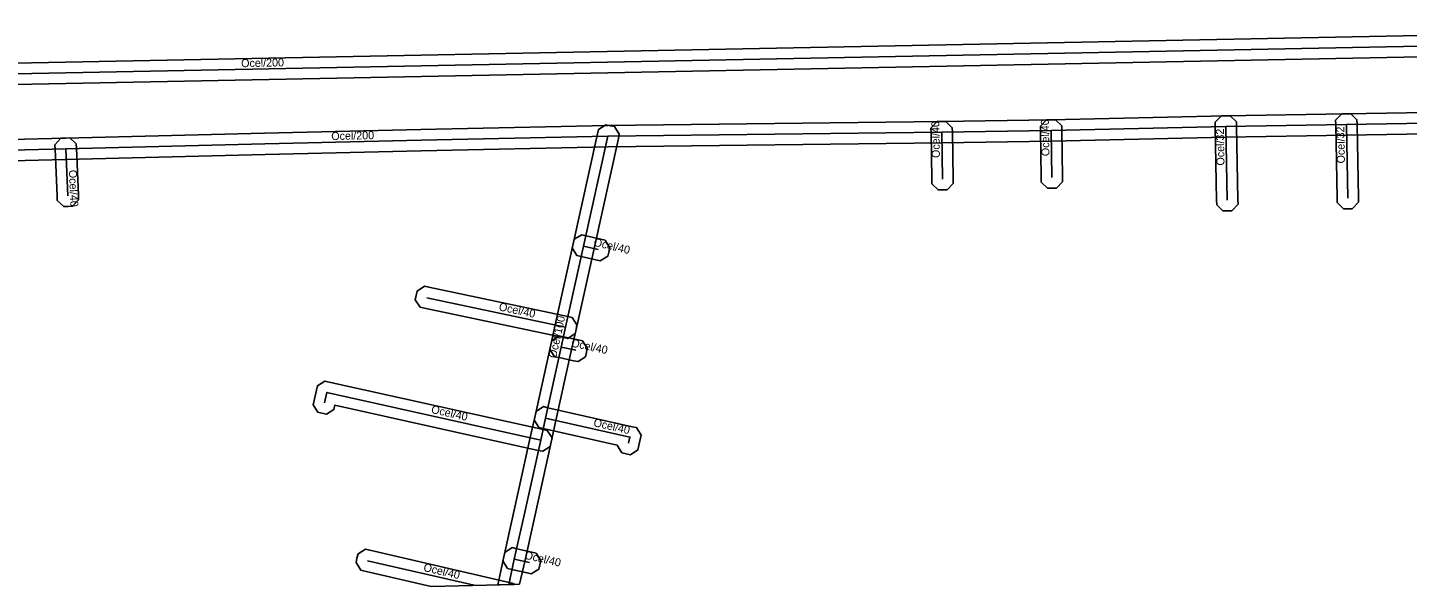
# Model space of a CAD drawing. Extents: x -702844 to -702342, y -1011731 to -1011542.
# Drawn here: x -702717.5 to -702588.2, y -1011727.3 to -1011674.9 of the extents above; entities that cross this region are included whole.
import ezdxf

# ---------------------------------------------------------------- set-up
doc = ezdxf.new("R2010")
doc.units = 0
for name, color, linetype in [('1', 7, 'Continuous'), ('14', 7, 'Continuous'), ('20', 7, 'Continuous'), ('24', 7, 'Continuous'), ('30', 7, 'Continuous')]:
    doc.layers.add(name, color=color, linetype=linetype)

msp = doc.modelspace()

# ---------------------------------------------------------------- linework, layer by layer
at = {"layer": '1'}
for points in [[(-702802.41, -1011681.9), (-702843.99, -1011682.6), (-702844.1, -1011680.6), (-702802.44, -1011679.9), (-702794.94, -1011679.78), (-702550.47, -1011674.95), (-702550.05, -1011674.94), (-702549.46, -1011675.51), (-702549.45, -1011675.93), (-702549.44, -1011676.34), (-702550.01, -1011676.94), (-702550.43, -1011676.95), (-702794.91, -1011681.78)], [(-702632.76, -1011689.58), (-702632.76, -1011689.16), (-702632.83, -1011684.76), (-702632.84, -1011684.35), (-702632.26, -1011683.75), (-702631.85, -1011683.75), (-702631.44, -1011683.74), (-702630.84, -1011684.32), (-702630.83, -1011684.73), (-702630.76, -1011689.13), (-702630.76, -1011689.55), (-702631.33, -1011690.14), (-702631.75, -1011690.15), (-702632.16, -1011690.15)], [(-702622.49, -1011689.41), (-702622.5, -1011689), (-702622.57, -1011684.6), (-702622.58, -1011684.19), (-702622, -1011683.59), (-702621.59, -1011683.58), (-702621.17, -1011683.58), (-702620.58, -1011684.15), (-702620.57, -1011684.57), (-702620.5, -1011688.97), (-702620.49, -1011689.38), (-702621.07, -1011689.98), (-702621.48, -1011689.98), (-702621.9, -1011689.99)], [(-702606.05, -1011691.54), (-702606.06, -1011691.12), (-702606.18, -1011684.22), (-702606.19, -1011683.81), (-702605.61, -1011683.21), (-702605.2, -1011683.21), (-702604.78, -1011683.2), (-702604.19, -1011683.78), (-702604.18, -1011684.19), (-702604.06, -1011691.09), (-702604.05, -1011691.5), (-702604.63, -1011692.1), (-702605.04, -1011692.1), (-702605.46, -1011692.11)], [(-702594.76, -1011691.34), (-702594.77, -1011690.93), (-702594.89, -1011684.03), (-702594.9, -1011683.62), (-702594.32, -1011683.02), (-702593.91, -1011683.01), (-702593.49, -1011683.01), (-702592.9, -1011683.58), (-702592.89, -1011684), (-702592.77, -1011690.9), (-702592.76, -1011691.31), (-702593.34, -1011691.91), (-702593.75, -1011691.91), (-702594.17, -1011691.92)], [(-702712.96, -1011685.83), (-702712.94, -1011686.24), (-702712.75, -1011690.65), (-702712.73, -1011691.07), (-702713.3, -1011691.68), (-702713.71, -1011691.69), (-702714.12, -1011691.71), (-702714.73, -1011691.15), (-702714.75, -1011690.74), (-702714.94, -1011686.33), (-702714.96, -1011685.92), (-702714.4, -1011685.31), (-702713.98, -1011685.29), (-702713.57, -1011685.27)], [(-702671.39, -1011727.11), (-702673.45, -1011727.16), (-702672.87, -1011724.53), (-702671.96, -1011720.44), (-702670.4, -1011713.37), (-702669.94, -1011711.32), (-702668.47, -1011704.67), (-702668.06, -1011702.8), (-702666.38, -1011695.2), (-702664.09, -1011684.9), (-702664, -1011684.49), (-702663.31, -1011684.05), (-702662.9, -1011684.14), (-702662.5, -1011684.22), (-702662.05, -1011684.92), (-702662.14, -1011685.33), (-702664.42, -1011695.63), (-702666.1, -1011703.23), (-702666.52, -1011705.1), (-702667.99, -1011711.75), (-702668.45, -1011713.8), (-702670.01, -1011720.87), (-702670.92, -1011724.97)], [(-702663.84, -1011696.81), (-702664.24, -1011696.71), (-702665.63, -1011696.39), (-702666.03, -1011696.3), (-702666.47, -1011695.59), (-702666.37, -1011695.19), (-702666.28, -1011694.78), (-702665.57, -1011694.35), (-702665.17, -1011694.44), (-702663.79, -1011694.77), (-702663.38, -1011694.86), (-702662.95, -1011695.57), (-702663.04, -1011695.97), (-702663.14, -1011696.37)], [(-702680.3, -1011699.18), (-702679.9, -1011699.27), (-702666.87, -1011702.03), (-702666.47, -1011702.12), (-702666.02, -1011702.81), (-702666.1, -1011703.22), (-702666.19, -1011703.62), (-702666.88, -1011704.08), (-702667.29, -1011703.99), (-702680.31, -1011701.23), (-702680.72, -1011701.14), (-702681.17, -1011700.45), (-702681.08, -1011700.04), (-702681, -1011699.64)], [(-702665.92, -1011706.24), (-702666.33, -1011706.16), (-702667.7, -1011705.87), (-702668.11, -1011705.78), (-702668.56, -1011705.09), (-702668.47, -1011704.68), (-702668.39, -1011704.28), (-702667.7, -1011703.82), (-702667.29, -1011703.91), (-702665.91, -1011704.2), (-702665.51, -1011704.28), (-702665.06, -1011704.98), (-702665.14, -1011705.38), (-702665.22, -1011705.79)], [(-702690.76, -1011710.29), (-702690.66, -1011709.88), (-702690.44, -1011708.91), (-702690.35, -1011708.51), (-702689.65, -1011708.07), (-702689.25, -1011708.16), (-702669.2, -1011712.61), (-702668.8, -1011712.7), (-702668.35, -1011713.4), (-702668.45, -1011713.8), (-702668.54, -1011714.21), (-702669.23, -1011714.65), (-702669.64, -1011714.56), (-702688.71, -1011710.32), (-702688.72, -1011710.33), (-702688.81, -1011710.74), (-702689.51, -1011711.18), (-702689.92, -1011711.08), (-702690.32, -1011710.99)], [(-702662.26, -1011714.08), (-702662.25, -1011714.07), (-702669.19, -1011712.51), (-702669.59, -1011712.42), (-702670.03, -1011711.71), (-702669.94, -1011711.31), (-702669.85, -1011710.91), (-702669.15, -1011710.46), (-702668.75, -1011710.56), (-702660.84, -1011712.34), (-702660.43, -1011712.43), (-702659.99, -1011713.13), (-702660.08, -1011713.53), (-702660.21, -1011714.12), (-702660.3, -1011714.52), (-702661.01, -1011714.97), (-702661.41, -1011714.88), (-702661.81, -1011714.78)], [(-702671.92, -1011727.12), (-702679.68, -1011727.31), (-702685.89, -1011725.88), (-702686.29, -1011725.78), (-702686.73, -1011725.08), (-702686.64, -1011724.68), (-702686.54, -1011724.27), (-702685.84, -1011723.83), (-702685.44, -1011723.93), (-702672.37, -1011726.95), (-702671.97, -1011727.04)], [(-702670.3, -1011726.14), (-702670.7, -1011726.05), (-702672.11, -1011725.72), (-702672.52, -1011725.63), (-702672.96, -1011724.93), (-702672.87, -1011724.53), (-702672.78, -1011724.12), (-702672.08, -1011723.68), (-702671.67, -1011723.78), (-702670.26, -1011724.09), (-702669.85, -1011724.19), (-702669.41, -1011724.89), (-702669.5, -1011725.29), (-702669.6, -1011725.7)]]:
    msp.add_lwpolyline(points, close=True, dxfattribs=at)
for points in [[(-702726.74, -1011685.61), (-702713.96, -1011685.29), (-702695.3, -1011684.82), (-702680.66, -1011684.5), (-702663.13, -1011684.11), (-702631.85, -1011683.75), (-702621.59, -1011683.58), (-702605.2, -1011683.21), (-702593.91, -1011683.01), (-702582.59, -1011682.82)], [(-702582.56, -1011684.82), (-702593.87, -1011685.01), (-702605.16, -1011685.21), (-702621.55, -1011685.58), (-702631.82, -1011685.75), (-702663.1, -1011686.11), (-702680.61, -1011686.5), (-702695.25, -1011686.82), (-702713.92, -1011687.29), (-702726.72, -1011687.61)]]:
    msp.add_lwpolyline(points, dxfattribs=at)
at = {"layer": '14'}
for points in [[(-702843.7, -1011687.87), (-702832.56, -1011687.68), (-702829.09, -1011687.62), (-702811.33, -1011687.3), (-702801.13, -1011687.01), (-702799.63, -1011687), (-702786.9, -1011686.9), (-702771.67, -1011686.78), (-702757.87, -1011686.66), (-702746.29, -1011686.56), (-702731.41, -1011686.6), (-702731.32, -1011686.6), (-702726.73, -1011686.61), (-702713.94, -1011686.29), (-702695.28, -1011685.82), (-702680.63, -1011685.5), (-702663.12, -1011685.11), (-702631.83, -1011684.75), (-702621.57, -1011684.58), (-702605.18, -1011684.21), (-702593.89, -1011684.01), (-702582.58, -1011683.82)], [(-702593.77, -1011690.91), (-702593.89, -1011684.01)], [(-702663.12, -1011685.11), (-702665.4, -1011695.42), (-702667.08, -1011703.01), (-702667.49, -1011704.89), (-702668.97, -1011711.53), (-702669.42, -1011713.59), (-702670.98, -1011720.65), (-702671.89, -1011724.75), (-702672.42, -1011727.14)], [(-702631.76, -1011689.15), (-702631.83, -1011684.75)], [(-702621.5, -1011688.98), (-702621.57, -1011684.58)], [(-702605.06, -1011691.1), (-702605.18, -1011684.21)], [(-702713.94, -1011686.29), (-702713.75, -1011690.7)], [(-702664.02, -1011695.74), (-702665.4, -1011695.42)], [(-702680.1, -1011700.25), (-702667.08, -1011703.01)], [(-702666.12, -1011705.18), (-702667.49, -1011704.89)], [(-702689.69, -1011710.11), (-702689.46, -1011709.13), (-702669.42, -1011713.59)], [(-702668.97, -1011711.53), (-702661.06, -1011713.31), (-702661.19, -1011713.9)], [(-702685.66, -1011724.9), (-702675.66, -1011727.21)], [(-702670.48, -1011725.07), (-702671.89, -1011724.75)]]:
    msp.add_lwpolyline(points, dxfattribs=at)
at = {"layer": '24'}
msp.add_lwpolyline([(-702550.45, -1011675.95), (-702794.92, -1011680.78), (-702802.43, -1011680.9), (-702844.04, -1011681.6)], dxfattribs=at)

# ---------------------------------------------------------------- texts
at = {"layer": '20'}
for s, rotation, p in [('Ocel/40', 90.9114, (-702632, -1011687.15)), ('Ocel/40', 90.9117, (-702621.73, -1011686.98)), ('Ocel/200', 1.2598, (-702689.04, -1011685.48)), ('Ocel/32', 90.9799, (-702605.32, -1011687.86)), ('Ocel/32', 90.9799, (-702594.03, -1011687.66)), ('Ocel/40', 272.4427, (-702713.65, -1011688.29)), ('Ocel/40', 346.7756, (-702664.51, -1011695.38)), ('Ocel/40', 348.0225, (-702673.39, -1011701.43)), ('Ocel/100', 77.5159, (-702667.98, -1011705.97)), ('Ocel/40', 348.1386, (-702666.61, -1011704.83)), ('Ocel/40', 347.4718, (-702679.73, -1011711.05)), ('Ocel/40', 347.3026, (-702664.52, -1011712.29)), ('Ocel/40', 347.2396, (-702670.99, -1011724.71)), ('Ocel/40', 346.973, (-702680.46, -1011725.86))]:
    msp.add_text(s, height=0.75, rotation=rotation, dxfattribs=at).set_placement(p)
at = {"layer": '30'}
msp.add_text('Ocel/200', height=0.75, rotation=1.1328, dxfattribs=at).set_placement((-702697.49, -1011678.65))

doc.saveas('drawing.dxf')
